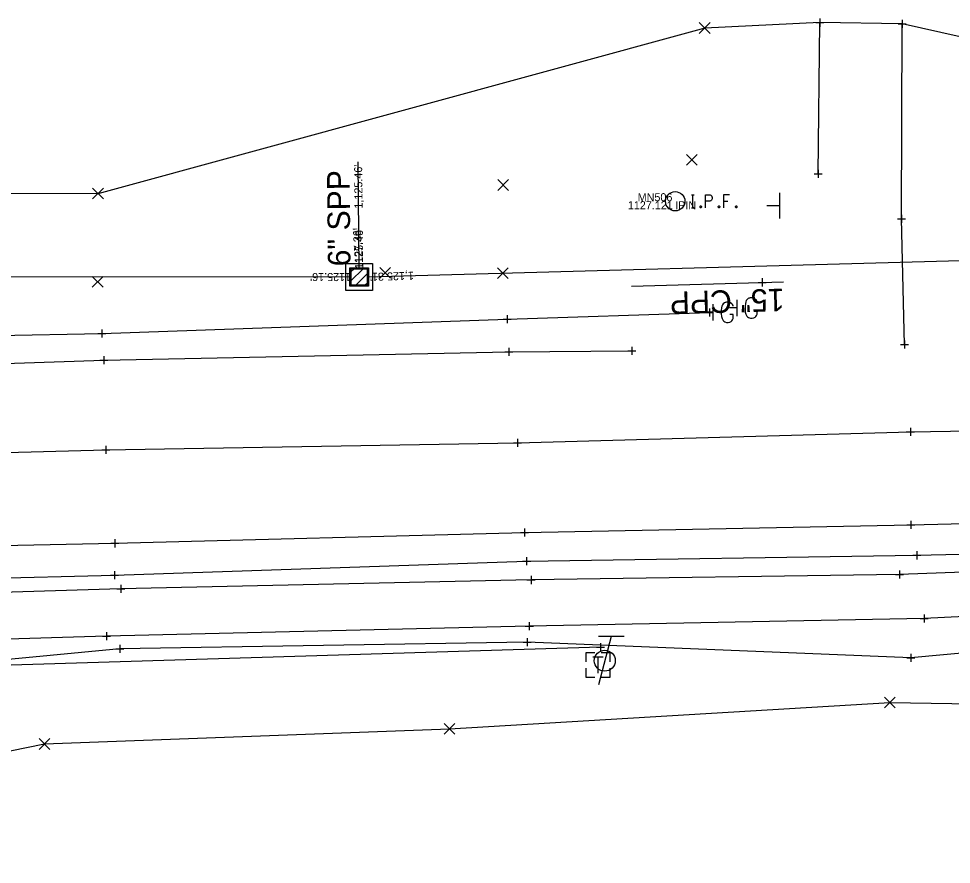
# Model space of a CAD drawing. Extents: x 2402028 to 2407435, y 498611 to 499105.
# Drawn here: x 2404124.6 to 2404240.4, y 498645 to 498750 of the extents above; entities that cross this region are included whole.
import ezdxf

# ---------------------------------------------------------------- set-up
doc = ezdxf.new("R2010")
doc.units = 0
for name, color, linetype in [('_CIVIL_CONSTRUCTION', 7, 'Continuous'), ('DR_X_Ditch', 7, 'Continuous'), ('DR_X_Storm_Sewer', 7, 'Continuous'), ('DR_X_Text', 7, 'Continuous'), ('PV_X_COP', 7, 'Continuous'), ('PV_X_EOP', 7, 'Continuous'), ('PV_X_Shoulder', 7, 'Continuous'), ('RW_X_CL_1000_Bearings', 7, 'Continuous'), ('RW_X_CL_1000_Cardinal_Points', 7, 'Continuous'), ('RW_X_CL_1000_Distances', 7, 'Continuous'), ('RW_X_CL_1000_Stations', 7, 'Continuous'), ('RW_X_CL_100_Bearings', 7, 'Continuous'), ('RW_X_CL_100_Cardinal_Points', 7, 'Continuous'), ('RW_X_CL_100_Distances', 7, 'Continuous'), ('RW_X_CL_100_Stations', 7, 'Continuous'), ('RW_X_CL_500_Bearings', 7, 'Continuous'), ('RW_X_CL_500_Stations', 7, 'Continuous'), ('SC_Scratch1', 7, 'Continuous'), ('SV_X_Break_Lines', 7, 'Continuous'), ('SV_X_Terrain_Boundary', 7, 'Continuous'), ('UT_X_Telecom', 7, 'Continuous')]:
    doc.layers.add(name, color=color, linetype=linetype)

msp = doc.modelspace()

# ---------------------------------------------------------------- linework, layer by layer
at = {"layer": 'DR_X_Ditch'}
msp.add_lwpolyline([(2404533.24, 498683.6), (2404485.13, 498682.32), (2404436.39, 498681.96), (2404386.54, 498679.04), (2404337.17, 498678.98), (2404287.56, 498677.96), (2404236.98, 498675.49), (2404187.96, 498674.52), (2404135.48, 498673.31), (2404086.4, 498671.8), (2404053.2, 498673.48), (2404047.02, 498674.14)], dxfattribs=at)
at = {"layer": 'DR_X_Storm_Sewer'}
for p, q in [((2404166.84, 498718.88), (2404166.7, 498732.17)), ((2404256.21, 498720.31), (2404167.84, 498717.88)), ((2404165.84, 498717.88), (2404056.73, 498717.91))]:
    msp.add_line(p, q, dxfattribs=at)
at = {"layer": 'DR_X_Text'}
msp.add_line((2404200.65, 498716.76), (2404219.51, 498717.27), dxfattribs=at)
at = {"layer": 'PV_X_COP'}
for points in [[(2404234.52, 498709.52), (2404234.15, 498725.11), (2404234.24, 498749.33)], [(2403985.57, 498692.23), (2404036.54, 498693.02), (2404085.82, 498695.1), (2404135.38, 498696.42), (2404186.49, 498697.31), (2404235.26, 498698.66), (2404284.95, 498699.47), (2404334.96, 498700.99), (2404383.89, 498702.2), (2404434.73, 498703.18), (2404484.39, 498704.35), (2404533.55, 498705.6)]]:
    msp.add_lwpolyline(points, dxfattribs=at)
at = {"layer": 'PV_X_EOP'}
for points in [[(2403338.61, 498686.54), (2403387.34, 498688.53), (2403437.74, 498689.31), (2403487.06, 498690.99), (2403539.21, 498692.01), (2403587.62, 498693.45), (2403637.16, 498694.45), (2403686.98, 498695.6), (2403736.54, 498696.76), (2403786.79, 498698.23), (2403836.48, 498699.49), (2403886.02, 498700.75), (2403935.9, 498702.14), (2403985.32, 498703.46), (2404035.9, 498704.57), (2404085.81, 498705.89), (2404135.13, 498707.56), (2404185.41, 498708.59), (2404200.68, 498708.71)], [(2403985.56, 498681.24), (2404036.04, 498682.2), (2404086.24, 498683.82), (2404136.5, 498684.82), (2404187.36, 498686.15), (2404235.32, 498687.11), (2404285.36, 498688.37), (2404336.4, 498689.7), (2404384.93, 498690.9), (2404435.67, 498692.09), (2404485.01, 498693.22), (2404533.25, 498694.59)]]:
    msp.add_lwpolyline(points, dxfattribs=at)
at = {"layer": 'PV_X_Shoulder'}
for p, q in [((2404223.82, 498730.7), (2404224.02, 498749.46)), ((2404134.88, 498710.88), (2404185.2, 498712.64)), ((2404185.2, 498712.64), (2404210.33, 498713.49)), ((2404085.38, 498709.86), (2404134.88, 498710.88))]:
    msp.add_line(p, q, dxfattribs=at)
msp.add_lwpolyline([(2403986.56, 498676.91), (2404036.95, 498678.51), (2404086.64, 498679.64), (2404136.45, 498680.88), (2404187.63, 498682.62), (2404236.08, 498683.33), (2404286.33, 498684.49), (2404336.81, 498686.17), (2404385.43, 498687.48), (2404436.29, 498688.5), (2404485.75, 498689.82), (2404533.69, 498691.17)], dxfattribs=at)
at = {"layer": 'RW_X_CL_1000_Bearings'}
for p, q in [((2404165.69, 498717.27), (2404167.45, 498719.03)), ((2404165.69, 498718.4), (2404166.32, 498719.03)), ((2404166.29, 498716.74), (2404167.98, 498718.43)), ((2404167.42, 498716.74), (2404167.98, 498717.3))]:
    msp.add_line(p, q, dxfattribs=at)
for points in [[(2404165.17, 498719.55), (2404168.5, 498719.55), (2404168.5, 498716.22), (2404165.17, 498716.22)], [(2404165.69, 498719.03), (2404167.98, 498719.03), (2404167.98, 498716.74), (2404165.69, 498716.74)], [(2404165.84, 498718.88), (2404167.84, 498718.88), (2404167.84, 498716.88), (2404165.84, 498716.88)]]:
    msp.add_lwpolyline(points, close=True, dxfattribs=at)
at = {"layer": 'RW_X_CL_1000_Cardinal_Points'}
for p, q in [((2404166.84, 498719.55), (2404166.84, 498719.55)), ((2404166.84, 498718.88), (2404166.84, 498718.88)), ((2404165.84, 498717.88), (2404165.84, 498717.88)), ((2404166.84, 498717.88), (2404166.84, 498717.88)), ((2404166.84, 498717.88), (2404166.84, 498717.88)), ((2404166.84, 498717.88), (2404166.84, 498717.88)), ((2404167.84, 498717.88), (2404167.84, 498717.88)), ((2404166.84, 498716.88), (2404166.84, 498716.88)), ((2404166.84, 498716.22), (2404166.84, 498716.22))]:
    msp.add_line(p, q, dxfattribs=at)
at = {"layer": 'RW_X_CL_1000_Distances'}
for p, q in [((2404199.73, 498673.25), (2404196.53, 498673.25)), ((2404198.13, 498673.25), (2404196.53, 498667.25)), ((2404195.84, 498670.71), (2404197.14, 498670.71)), ((2404196.49, 498668.71), (2404196.49, 498670.71)), ((2404196.49, 498669.71), (2404196.49, 498669.71))]:
    msp.add_line(p, q, dxfattribs=at)
for points in [[(2404196.09, 498671.21), (2404194.99, 498671.21), (2404194.99, 498670.11)], [(2404197.99, 498670.11), (2404197.99, 498671.21), (2404196.89, 498671.21)], [(2404194.99, 498669.31), (2404194.99, 498668.21), (2404196.09, 498668.21)], [(2404196.89, 498668.21), (2404197.99, 498668.21), (2404197.99, 498669.31)]]:
    msp.add_lwpolyline(points, dxfattribs=at)
msp.add_circle((2404197.33, 498670.25), 1.3, dxfattribs=at)
at = {"layer": 'RW_X_CL_1000_Stations'}
for p, q in [((2404219.03, 498728.33), (2404219.03, 498725.13)), ((2404219.03, 498726.73), (2404217.43, 498726.73))]:
    msp.add_line(p, q, dxfattribs=at)
at = {"layer": 'RW_X_CL_100_Distances'}
for p, q in [((2404213.75, 498713.04), (2404213.75, 498715.04)), ((2404210.79, 498712.5), (2404210.79, 498714.5)), ((2404213.75, 498714.04), (2404212.8, 498714.04)), ((2404210.79, 498713.5), (2404209.84, 498713.5))]:
    msp.add_line(p, q, dxfattribs=at)
for points in [[(2404216.23, 498714.8), (2404216.21, 498714.89), (2404216.15, 498714.99), (2404216.05, 498715.09), (2404215.91, 498715.21), (2404215.81, 498715.25), (2404215.73, 498715.27), (2404215.62, 498715.29), (2404215.38, 498715.29), (2404215.28, 498715.27), (2404215.22, 498715.25), (2404215.14, 498715.21), (2404214.99, 498715.09), (2404214.89, 498714.95), (2404214.83, 498714.8), (2404214.79, 498714.58), (2404214.75, 498714.26), (2404214.75, 498713.85), (2404214.77, 498713.52), (2404214.85, 498713.26), (2404214.97, 498713.02), (2404215.06, 498712.95), (2404215.18, 498712.87), (2404215.4, 498712.79), (2404215.62, 498712.79), (2404215.83, 498712.83), (2404215.91, 498712.87), (2404215.99, 498712.91), (2404216.07, 498712.99), (2404216.15, 498713.1), (2404216.23, 498713.28), (2404216.23, 498713.77), (2404215.81, 498713.77)], [(2404213.27, 498714.26), (2404213.25, 498714.36), (2404213.19, 498714.45), (2404213.09, 498714.55), (2404212.95, 498714.67), (2404212.85, 498714.71), (2404212.77, 498714.73), (2404212.66, 498714.75), (2404212.42, 498714.75), (2404212.32, 498714.73), (2404212.26, 498714.71), (2404212.18, 498714.67), (2404212.03, 498714.55), (2404211.93, 498714.41), (2404211.87, 498714.26), (2404211.83, 498714.04), (2404211.79, 498713.73), (2404211.79, 498713.31), (2404211.81, 498712.98), (2404211.89, 498712.72), (2404212.01, 498712.49), (2404212.1, 498712.41), (2404212.22, 498712.33), (2404212.44, 498712.25), (2404212.66, 498712.25), (2404212.87, 498712.29), (2404212.95, 498712.33), (2404213.03, 498712.37), (2404213.11, 498712.45), (2404213.19, 498712.56), (2404213.27, 498712.74), (2404213.27, 498713.23), (2404212.85, 498713.23)]]:
    msp.add_lwpolyline(points, dxfattribs=at)
at = {"layer": 'RW_X_CL_100_Stations'}
for points in [[(2404208.08, 498728.09), (2404208.43, 498728.09)], [(2404208.26, 498726.49), (2404208.26, 498728.09)], [(2404209.82, 498726.49), (2404209.82, 498728.09), (2404210.35, 498728.09), (2404210.41, 498728.07), (2404210.48, 498728.05), (2404210.52, 498728.02), (2404210.55, 498728), (2404210.6, 498727.93), (2404210.63, 498727.87), (2404210.65, 498727.77), (2404210.65, 498727.62), (2404210.64, 498727.57), (2404210.62, 498727.49), (2404210.57, 498727.41), (2404210.53, 498727.37), (2404210.5, 498727.34), (2404210.44, 498727.32), (2404210.35, 498727.3), (2404209.82, 498727.3)], [(2404212.83, 498728.09), (2404212.07, 498728.09), (2404212.07, 498726.49)], [(2404208.08, 498726.49), (2404208.43, 498726.49)], [(2404209.22, 498726.7), (2404209.27, 498726.7), (2404209.31, 498726.67), (2404209.34, 498726.62), (2404209.34, 498726.56), (2404209.31, 498726.51), (2404209.27, 498726.49), (2404209.22, 498726.49), (2404209.18, 498726.51), (2404209.15, 498726.56), (2404209.15, 498726.62), (2404209.18, 498726.67), (2404209.22, 498726.7)], [(2404211.47, 498726.7), (2404211.52, 498726.7), (2404211.55, 498726.67), (2404211.59, 498726.62), (2404211.59, 498726.56), (2404211.55, 498726.51), (2404211.52, 498726.49), (2404211.47, 498726.49), (2404211.43, 498726.51), (2404211.4, 498726.56), (2404211.4, 498726.62), (2404211.43, 498726.67), (2404211.47, 498726.7)], [(2404212.07, 498727.3), (2404212.61, 498727.3)], [(2404213.62, 498726.7), (2404213.67, 498726.7), (2404213.7, 498726.67), (2404213.74, 498726.62), (2404213.74, 498726.56), (2404213.7, 498726.51), (2404213.67, 498726.49), (2404213.62, 498726.49), (2404213.58, 498726.51), (2404213.55, 498726.56), (2404213.55, 498726.62), (2404213.58, 498726.67), (2404213.62, 498726.7)]]:
    msp.add_lwpolyline(points, dxfattribs=at)
msp.add_circle((2404206.07, 498727.29), 1.2, dxfattribs=at)
at = {"layer": 'RW_X_CL_500_Bearings'}
for p, q in [((2404224.02, 498749.96), (2404224.02, 498748.96)), ((2404234.24, 498749.83), (2404234.24, 498748.83)), ((2404223.52, 498749.46), (2404224.52, 498749.46)), ((2404224.02, 498749.46), (2404224.02, 498749.46)), ((2404233.74, 498749.33), (2404234.74, 498749.33)), ((2404234.24, 498749.33), (2404234.24, 498749.33)), ((2404223.82, 498731.2), (2404223.82, 498730.2)), ((2404223.32, 498730.7), (2404224.32, 498730.7)), ((2404223.82, 498730.7), (2404223.82, 498730.7)), ((2404234.15, 498725.61), (2404234.15, 498724.61)), ((2404233.65, 498725.11), (2404234.65, 498725.11)), ((2404234.15, 498725.11), (2404234.15, 498725.11)), ((2404216.35, 498717.22), (2404217.35, 498717.22)), ((2404216.85, 498717.72), (2404216.85, 498716.72)), ((2404216.85, 498717.22), (2404216.85, 498717.22)), ((2404210.33, 498713.99), (2404210.33, 498712.99)), ((2404184.7, 498712.64), (2404185.7, 498712.64)), ((2404185.2, 498713.14), (2404185.2, 498712.14)), ((2404185.2, 498712.64), (2404185.2, 498712.64)), ((2404209.83, 498713.49), (2404210.83, 498713.49)), ((2404210.33, 498713.49), (2404210.33, 498713.49)), ((2404134.88, 498711.38), (2404134.88, 498710.38)), ((2404134.38, 498710.88), (2404135.38, 498710.88)), ((2404134.88, 498710.88), (2404134.88, 498710.88)), ((2404185.41, 498709.09), (2404185.41, 498708.09)), ((2404200.68, 498709.21), (2404200.68, 498708.21)), ((2404234.02, 498709.52), (2404235.02, 498709.52)), ((2404234.52, 498710.02), (2404234.52, 498709.02)), ((2404234.52, 498709.52), (2404234.52, 498709.52)), ((2404135.13, 498708.06), (2404135.13, 498707.06)), ((2404184.91, 498708.59), (2404185.91, 498708.59)), ((2404185.41, 498708.59), (2404185.41, 498708.59)), ((2404200.18, 498708.71), (2404201.18, 498708.71)), ((2404200.68, 498708.71), (2404200.68, 498708.71)), ((2404134.63, 498707.56), (2404135.63, 498707.56)), ((2404135.13, 498707.56), (2404135.13, 498707.56)), ((2404234.76, 498698.66), (2404235.76, 498698.66)), ((2404235.26, 498699.16), (2404235.26, 498698.16)), ((2404235.26, 498698.66), (2404235.26, 498698.66)), ((2404186.49, 498697.81), (2404186.49, 498696.81)), ((2404134.88, 498696.42), (2404135.88, 498696.42)), ((2404135.38, 498696.92), (2404135.38, 498695.92)), ((2404135.38, 498696.42), (2404135.38, 498696.42)), ((2404185.99, 498697.31), (2404186.99, 498697.31)), ((2404186.49, 498697.31), (2404186.49, 498697.31)), ((2404234.82, 498687.11), (2404235.82, 498687.11)), ((2404235.32, 498687.61), (2404235.32, 498686.61)), ((2404235.32, 498687.11), (2404235.32, 498687.11)), ((2404186.86, 498686.15), (2404187.86, 498686.15)), ((2404187.36, 498686.65), (2404187.36, 498685.65)), ((2404187.36, 498686.15), (2404187.36, 498686.15)), ((2404136, 498684.82), (2404137, 498684.82)), ((2404136.5, 498685.32), (2404136.5, 498684.32)), ((2404136.5, 498684.82), (2404136.5, 498684.82)), ((2404236.08, 498683.83), (2404236.08, 498682.83)), ((2404187.13, 498682.62), (2404188.13, 498682.62)), ((2404187.63, 498683.12), (2404187.63, 498682.12)), ((2404187.63, 498682.62), (2404187.63, 498682.62)), ((2404235.58, 498683.33), (2404236.58, 498683.33)), ((2404236.08, 498683.33), (2404236.08, 498683.33)), ((2404136.45, 498681.38), (2404136.45, 498680.38)), ((2404233.91, 498681.45), (2404233.91, 498680.45)), ((2404135.95, 498680.88), (2404136.95, 498680.88)), ((2404136.45, 498680.88), (2404136.45, 498680.88)), ((2404187.67, 498680.27), (2404188.67, 498680.27)), ((2404188.17, 498680.77), (2404188.17, 498679.77)), ((2404188.17, 498680.27), (2404188.17, 498680.27)), ((2404233.41, 498680.95), (2404234.41, 498680.95)), ((2404233.91, 498680.95), (2404233.91, 498680.95)), ((2404136.74, 498679.18), (2404137.74, 498679.18)), ((2404137.24, 498679.68), (2404137.24, 498678.68)), ((2404137.24, 498679.18), (2404137.24, 498679.18)), ((2404236.48, 498675.49), (2404237.48, 498675.49)), ((2404236.98, 498675.99), (2404236.98, 498674.99)), ((2404236.98, 498675.49), (2404236.98, 498675.49)), ((2404187.46, 498674.52), (2404188.46, 498674.52)), ((2404187.96, 498675.02), (2404187.96, 498674.02)), ((2404187.96, 498674.52), (2404187.96, 498674.52)), ((2404134.98, 498673.31), (2404135.98, 498673.31)), ((2404135.48, 498673.81), (2404135.48, 498672.81)), ((2404135.48, 498673.31), (2404135.48, 498673.31)), ((2404137.13, 498672.23), (2404137.13, 498671.23)), ((2404187.18, 498672.55), (2404188.18, 498672.55)), ((2404187.68, 498673.05), (2404187.68, 498672.05)), ((2404187.68, 498672.55), (2404187.68, 498672.55)), ((2404196.79, 498672.41), (2404196.79, 498671.41)), ((2404136.63, 498671.73), (2404137.63, 498671.73)), ((2404137.13, 498671.73), (2404137.13, 498671.73)), ((2404196.29, 498671.91), (2404197.29, 498671.91)), ((2404196.79, 498671.91), (2404196.79, 498671.91)), ((2404235.32, 498671.12), (2404235.32, 498670.12)), ((2404234.82, 498670.62), (2404235.82, 498670.62)), ((2404235.32, 498670.62), (2404235.32, 498670.62))]:
    msp.add_line(p, q, dxfattribs=at)
at = {"layer": 'RW_X_CL_500_Stations'}
for p, q in [((2404209.06, 498748.12), (2404210.39, 498749.46)), ((2404209.06, 498749.46), (2404210.39, 498748.12)), ((2404207.48, 498731.77), (2404208.81, 498733.11)), ((2404207.48, 498733.11), (2404208.81, 498731.77)), ((2404184.06, 498728.64), (2404185.39, 498729.98)), ((2404184.06, 498729.98), (2404185.39, 498728.64)), ((2404133.74, 498727.57), (2404135.08, 498728.9)), ((2404133.74, 498728.9), (2404135.08, 498727.57)), ((2404169.39, 498717.74), (2404170.72, 498719.08)), ((2404169.39, 498719.08), (2404170.72, 498717.74)), ((2404184, 498717.71), (2404185.33, 498719.04)), ((2404184, 498719.04), (2404185.33, 498717.71)), ((2404133.71, 498716.61), (2404135.04, 498717.95)), ((2404133.71, 498717.95), (2404135.04, 498716.61)), ((2404232.06, 498664.4), (2404233.39, 498665.74)), ((2404232.06, 498665.74), (2404233.39, 498664.4)), ((2404177.4, 498661.13), (2404178.73, 498662.47)), ((2404177.4, 498662.47), (2404178.73, 498661.13)), ((2404127.11, 498659.24), (2404128.45, 498660.58)), ((2404127.11, 498660.58), (2404128.45, 498659.24))]:
    msp.add_line(p, q, dxfattribs=at)
at = {"layer": 'SV_X_Break_Lines'}
for points in [[(2404534.29, 498688.61), (2404486.42, 498687.58), (2404437.42, 498686.5), (2404385.81, 498685.86), (2404336.79, 498684.01), (2404286.16, 498682.85), (2404233.91, 498680.95), (2404188.17, 498680.27), (2404137.24, 498679.18), (2404087.21, 498677.64), (2404055.25, 498678.14)], [(2404534.06, 498678.67), (2404487.14, 498679.19), (2404435.91, 498680.7), (2404386.18, 498676.8), (2404335.53, 498673.1), (2404285.8, 498675.24), (2404235.32, 498670.62), (2404187.68, 498672.55), (2404137.13, 498671.73), (2404087.36, 498666.97), (2404054.4, 498671.14), (2404059.39, 498667.3)]]:
    msp.add_lwpolyline(points, dxfattribs=at)
at = {"layer": 'SV_X_Terrain_Boundary'}
for points in [[(2404243.83, 498747.15), (2404234.24, 498749.33), (2404224.02, 498749.46), (2404209.73, 498748.79), (2404134.41, 498728.23), (2404084.34, 498728.27), (2404013.92, 498724.8), (2403983.78, 498725.5)], [(2403985.55, 498656.18), (2404071.93, 498644.97), (2404075.01, 498646.62), (2404074.36, 498649.06), (2404127.78, 498659.91), (2404178.06, 498661.8), (2404232.73, 498665.07), (2404291.58, 498664.1)]]:
    msp.add_lwpolyline(points, dxfattribs=at)
at = {"layer": 'UT_X_Telecom'}
msp.add_lwpolyline([(2404196.79, 498671.91), (2404031.46, 498666.86)], dxfattribs=at)

# ---------------------------------------------------------------- texts
at = {"layer": '_CIVIL_CONSTRUCTION'}
msp.add_text('MN506', height=1, dxfattribs=at).set_placement((2404201.41, 498727.29))
at = {"layer": 'DR_X_Text'}
for s, rotation, p in [('6" SPP', 90.5698, (2404165.76, 498719.22)), ('15" CPP', 181.5699, (2404219.59, 498716.45))]:
    msp.add_text(s, height=2.8, rotation=rotation, dxfattribs=at).set_placement(p)
at = {"layer": 'RW_X_CL_100_Bearings'}
msp.add_text('1127.121', height=1, dxfattribs=at).set_placement((2404200.19, 498726.29))
at = {"layer": 'RW_X_CL_100_Cardinal_Points'}
msp.add_text('IPIN', height=1, dxfattribs=at).set_placement((2404206.07, 498726.29))
at = {"layer": 'SC_Scratch1'}
for s, rotation, p in [("1,125.46'", 90.5698, (2404167.26, 498726.38)), ("1127.36'", 93.3706, (2404167.34, 498718.91)), ("1125.46'", 90.5698, (2404167.34, 498718.89)), ("1125.16'", 179.9879, (2404165.84, 498718.38)), ("1,125.31'", 181.5699, (2404173.62, 498718.54))]:
    msp.add_text(s, height=1, rotation=rotation, dxfattribs=at).set_placement(p)

doc.saveas('drawing.dxf')
